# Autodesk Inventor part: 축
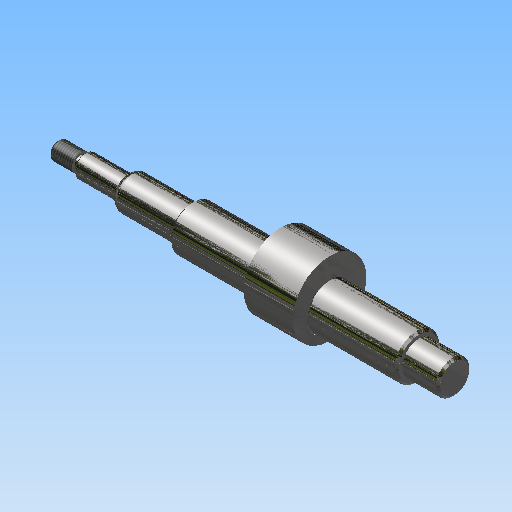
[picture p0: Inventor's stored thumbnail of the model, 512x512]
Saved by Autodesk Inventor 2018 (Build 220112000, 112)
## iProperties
Created: 2015-12
Part Number: 축
Document SubType Name: Modeling
Designer: mdu
Density: 7.86 g/cm^3
Material: 강철, 연강
Mass: 421.834 g
Surface Area: 119.066 cm^2
Volume: 53.6685 cm^3
Appearance: 반광택
Author: mdu
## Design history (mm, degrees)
sketch "스케치1"
  geometry: L1 (62, 100.9)-(62, 67.1) reference; L2 (51, 101.2)-(51, 84) reference; L3 (-51, 84)-(-51, 101.2) reference; L4 (-62, 67.1)-(-62, 100.9) reference; L5 (-51.6, 91.5)-(-61.4, 91.5) reference; L6 (51.6, 91.5)-(61.4, 91.5) reference; L7 (67, 84)-(-111, 84); L8 (-77, 64.201)-(-77, 103.799) reference; L9 (67, 84)-(67, 91.5); L10 (67, 91.5)-(51, 91.5); L11 (51, 91.5)-(51, 94); L12 (51, 94)-(-51, 94); L13 (-51, 94)-(-51, 91.5); L14 (-51, 91.5)-(-79, 91.5); L15 (-79, 91.5)-(-79, 89); L16 (-79, 89)-(-99, 89); L17 (-99, 89)-(-99, 87); L18 (-100.5, 88)-(-111, 88); L19 (-111, 88)-(-111, 84); L20 (-99, 87)-(-100.5, 87); L21 (-100.5, 87)-(-100.5, 88); 2 further points
  constraints: 32 end point, 7 parallel, 6 point on line, 5 perpendicular, 2 collinear, 2 horizontal, 1 midpoint, 4 other
  dimensions: "d0" = 5 distance from line of L7.start L1; "d2" = 2 distance between parallel lines of L15 L8; "d3" = 20 diameter of L12 L7; "d4" = 10 diameter of L16 L7; "d5" = 1.5 distance of L17.end L20.end; "d6" = 6 diameter of L20 L7; "d7" = 20 distance of L15.end L16.end; "d8" = 12 distance between parallel lines of L17 L19; "d9" = 8 diameter of L18 L7
revolve "회전1" sketch "스케치1" stored, may be unused: angle "d10" = 90 deg
sketch "스케치2"
  geometry: C1 r 10 at (84, 0) reference; C2 r 10 at (84, 0) reference; C3 r 16.5 at (87, 0); 1 further point
  constraints: 1 centre point, 1 horizontal alignment
  dimensions: "d11" = 33 diameter of C3; "d12" = 3 distance of C3.centre C1.centre
extrude "돌출1" join sketch "스케치2" stored distance "d13" = 22; taper "d14" = 0 deg
chamfer "모따기1" distance "d15" = 1; stored, may be unused: second distance "d16" = 2, angle "d17" = 45 deg
feature "스레드1" dims "d18" = 10, "d19" = 0
node "작업 평면1"
sketch "스케치3"
  geometry: L1 (-5.5, -1.5)-(3.5, -1.5); L2 (3.5, 1.5)-(-5.5, 1.5); L3 (-10, -4)-(-10, 4) reference; A1 r 1.5 centre (3.5, 0) between (3.5, -1.5) and (3.5, 1.5); A2 r 1.5 centre (-5.5, 0) between (-5.5, 1.5) and (-5.5, -1.5); 2 further points
  constraints: 4 end point, 4 point on circle, 4 tangent, 2 centre point, 1 horizontal, 1 horizontal alignment, 1 midpoint, 1 parallel
  dimensions: "d20" = 3 distance between parallel lines of L1 L2; "d21" = 12 dimension on A1 A2; "d22" = 3 distance edge to line of A2 L3
extrude "돌출2" cut sketch "스케치3" distance "d23" = 1.8; taper "d24" = 0 deg
fillet "모깎기1" dims "d25" = 0.3
fillet "모깎기2" dims "d26" = 3
node "솔리드1"
node "참조1"
node "참조2"
node "참조3"
node "참조4"
node "참조5"
node "투영된 루프1"
